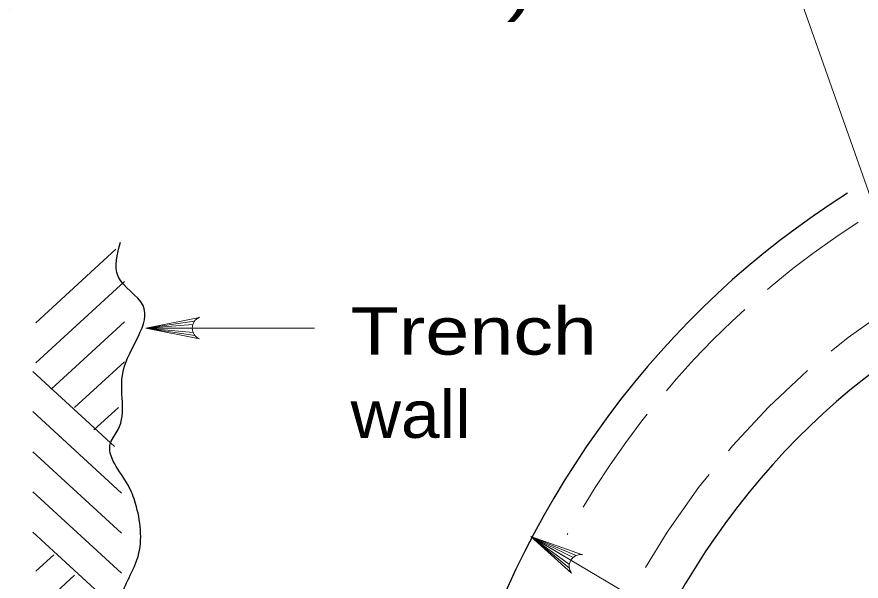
# Model space of a CAD drawing. Extents: x 1170.6 to 1204.6, y 975 to 1019.
# Drawn here: x 1188.12 to 1190.902, y 1004.106 to 1005.964 of the extents above; entities that cross this region are included whole.
import ezdxf

# ---------------------------------------------------------------- set-up
doc = ezdxf.new("R2010")
doc.units = 0
doc.header["$LTSCALE"] = 0.062
doc.linetypes.add('LONG_DASHED', pattern=[7.5, 6, -1.5])
doc.layers.add('1', color=7, linetype='Continuous', lineweight=13)

msp = doc.modelspace()

# ---------------------------------------------------------------- linework, layer by layer
at = {"layer": '1'}
for p, q in [((1191.01183, 1005.14358), (1190.68867, 1006.06167)), ((1188.4465, 1005.19867), (1188.1825, 1004.9565)), ((1188.47483, 1005.09233), (1188.1825, 1004.82425)), ((1188.47483, 1004.96008), (1188.23283, 1004.73825)), ((1188.70525, 1004.96142), (1188.545, 1004.93892)), ((1188.69983, 1004.95025), (1188.545, 1004.93892)), ((1188.59667, 1004.93892), (1188.545, 1004.93892)), ((1188.545, 1004.93892), (1189.10125, 1004.93892)), ((1188.69817, 1004.93892), (1188.545, 1004.93892)), ((1188.701, 1004.92458), (1188.545, 1004.93892)), ((1188.70708, 1004.91417), (1188.545, 1004.93892)), ((1188.47483, 1004.82792), (1188.3105, 1004.67725)), ((1188.44208, 1004.54942), (1188.17308, 1004.79608)), ((1188.45508, 1004.67758), (1188.37425, 1004.6035)), ((1188.46533, 1004.39583), (1188.17308, 1004.66383)), ((1188.46533, 1004.26367), (1188.17308, 1004.53167)), ((1188.46533, 1004.13142), (1188.17308, 1004.3995)), ((1188.43708, 1004.02517), (1188.17308, 1004.26725)), ((1189.94558, 1004.1745), (1189.81383, 1004.25258)), ((1189.94067, 1004.16067), (1189.81383, 1004.25258)), ((1189.94067, 1004.14867), (1189.81383, 1004.25258)), ((1189.95275, 1004.18342), (1189.81383, 1004.25258)), ((1189.96308, 1004.19017), (1189.81383, 1004.25258)), ((1188.24208, 1004.19283), (1188.18308, 1004.13867)), ((1188.3105, 1004.12542), (1188.18108, 1004.00675))]:
    msp.add_line(p, q, dxfattribs=at)
for points in [[(1188.722, 1004.90358), (1188.545, 1004.93892), (1188.722, 1004.97433)], [(1189.948, 1004.13192), (1189.81383, 1004.25258), (1189.98408, 1004.19283)], [(1191.22567, 1003.41608), (1190.316, 1003.95508), (1189.81383, 1004.25258)]]:
    msp.add_lwpolyline(points, dxfattribs=at)
for centre, start, end in [((1188.73628, 1004.93899), 112.08782, 247.91395), ((1189.9784, 1004.15512), 81.44179, 217.26791)]:
    msp.add_arc(centre, 0.0382, start, end, dxfattribs=at)
at = {"layer": '1', "lineweight": 25}
for centre, major_axis, start_param, end_param in [((1192.32696, 1002.75942), (0, 2.50862), 4.2253836, 7.3170107), ((1192.33349, 1002.76462), (0, 3.04986), 0.5380125, 3.4065639)]:
    msp.add_ellipse(centre, major_axis=major_axis, ratio=0.944544, start_param=start_param, end_param=end_param, dxfattribs=at)
at = {"layer": '1', "linetype": 'LONG_DASHED'}
for centre, major_axis, start_param, end_param in [((1192.31467, 1002.75942), (0, 2.64426), 6.2228396, 7.3171666), ((1192.32486, 1002.77617), (0, 2.93373), 0.5434027, 1.0409678)]:
    msp.add_ellipse(centre, major_axis=major_axis, ratio=0.944544, start_param=start_param, end_param=end_param, dxfattribs=at)
at = {"layer": '1', "lineweight": 25}
msp.add_spline([(1188.46058, 1003.92492), (1188.462, 1004.04767), (1188.5195, 1004.18692), (1188.51133, 1004.36092), (1188.48667, 1004.42183), (1188.42917, 1004.561), (1188.45383, 1004.60458), (1188.47025, 1004.79592), (1188.53592, 1005.0135), (1188.45383, 1005.10917), (1188.462, 1005.22167)], degree=3, dxfattribs=at)

# ---------------------------------------------------------------- texts
at = {"layer": '1'}
for s, width, p in [('(See TABLE 1, Sheet 2 of 2.)', 1.3, (1186.31108, 1005.99325)), ('Trench', 1.25, (1189.21992, 1004.85142)), ('wall', 1.1, (1189.21992, 1004.57742))]:
    msp.add_text(s, height=0.156, dxfattribs=dict(at, width=width)).set_placement(p)

doc.saveas('drawing.dxf')
